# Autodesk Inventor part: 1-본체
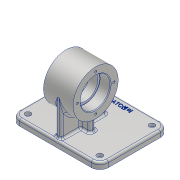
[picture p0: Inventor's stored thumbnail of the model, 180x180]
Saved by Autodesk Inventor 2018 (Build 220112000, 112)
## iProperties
Created: 2019-09
Part Number: 1-본체
Material: 알루미늄 6061
Document SubType Name: Modeling
Designer: USER
Density: 2.7 g/cm^3
Appearance: 알루미늄 - 평지
Mass: 554.62 g
Surface Area: 495.884 cm^2
Volume: 205.415 cm^3
Author: USER
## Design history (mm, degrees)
sketch "스케치1"
  geometry: L1 (-63, -49)-(63, -49); L2 (63, -49)-(63, 49); L3 (63, 49)-(-63, 49); L4 (-63, 49)-(-63, -49); L5 (-63, -49)-(63, 49); L6 (63, -49)-(-63, 49); 1 further point
  constraints: 12 end point, 2 midpoint, 2 parallel, 1 horizontal, 1 perpendicular
  dimensions: "d0" = 126 distance of L2.end L3.end; "d1" = 98 distance of L1.end L2.end
extrude "돌출1" new body sketch "스케치1" distance "d2" = 9; taper "d3" = 0 deg
sketch "스케치2"
  geometry: L1 (-49, 0)-(-49, 9) reference; L2 (49, 0)-(-49, 0) reference; C1 r 32 at (-13, 59); 1 further point
  constraints: 1 centre point
  dimensions: "d4" = 36 distance from line of L1 C1.centre; "d5" = 64 diameter of C1; "d6" = 59 distance from line of L2 C1.centre
extrude "돌출2" join sketch "스케치2" stored distance "d7" = 42; taper "d8" = 0 deg
sketch "스케치3"
  geometry: L1 (-45, 59)-(19, 59); L2 (19, 59)-(19, 0); L3 (19, 0)-(-45, 0); L4 (-45, 0)-(-45, 59); 2 further points
  constraints: 8 end point, 2 parallel, 1 horizontal, 1 horizontal alignment, 1 perpendicular, 1 other
  dimensions: "d9" = 64 distance between parallel lines of L2 L4; "d10" = 59 distance between parallel lines of L3 L1
extrude "돌출3" join sketch "스케치3" stored distance "d11" = 8; taper "d12" = 0 deg
sketch "스케치4"
  geometry: L1 (49, 0)-(-49, 0) reference; L2 (-17, 59)-(-9, 59); L3 (-9, 59)-(-9, 0); L4 (-9, 0)-(-17, 0); L5 (-17, 0)-(-17, 59); L6 (-49, 0)-(-49, 9) reference; L7 (-49, 9)-(-45, 9) reference; L8 (-45, 9)-(-45, 59) reference; L9 (19, 59)-(19, 9) reference; L10 (19, 9)-(49, 9) reference; L11 (49, 9)-(49, 0) reference; L12 (49, 0)-(-49, 0) reference; L13 (-49, 0)-(-49, 9) reference; L14 (-49, 9)-(-45, 9) reference; L15 (-45, 9)-(-45, 59) reference; L16 (19, 59)-(19, 9) reference; L17 (19, 9)-(49, 9) reference; L18 (49, 9)-(49, 0) reference; L19 (49, 0)-(-49, 0) reference; A1 r 32 centre (-13, 59) between (19, 59) and (-45, 59) reference; A2 r 32 centre (-13, 59) between (19, 59) and (-45, 59) reference; 1 further point
  constraints: 8 end point, 2 parallel, 1 horizontal, 1 perpendicular, 1 point on line
  dimensions: "d13" = 8 distance between parallel lines of L3 L5; "d14" = 59 distance between parallel lines of L1 L2; "d15" = 4 distance from line of L3 A1.centre
extrude "돌출4" join sketch "스케치4" stored distance "d16" = 34; taper "d17" = 0 deg
sketch "스케치5"
  geometry: C1 r 32 at (0, 0) reference; 2 further points
  constraints: 1 coincident
hole "구멍1" sketch "스케치5" at (0, 0) diameter "d18" = 36; stored, may be unused: countersink angle "d22" = 90 deg, drill point angle "d24" = 118 deg; dims "d19" = 6, "d20" = 42, "d21" = 15, "d23" = 36
node "작업 평면1"
sketch "스케치6" dims "d25" = 52
  geometry: A1 r 32 centre (0, 0) between (-31.749, -4) and (0, -32) reference; 3 further points
  constraints: 1 coincident, 1 horizontal alignment, 2 other
hole "구멍2" sketch "스케치6" at (26, 0) diameter "d26" = 3.242; stored, may be unused: countersink angle "d30" = 90 deg, drill point angle "d32" = 118 deg; dims "d27" = 8, "d28" = 42, "d29" = 15, "d31" = 10
sketch "스케치7"
  geometry: L1 (4, -9)-(17, -9) reference; L2 (17, -9)-(17, -17) reference; L3 (17, -17)-(4, -17) reference; L4 (4, -17)-(4, -45) reference; L5 (4, -45)-(-4, -45) reference; L6 (-4, -45)-(-4, -17) reference; L7 (-4, -17)-(-17, -17) reference; L8 (-17, -17)-(-17, -9) reference; L9 (-17, -9)-(-4, -9) reference; L10 (-4, -9)-(-4, 19) reference; L11 (-4, 19)-(4, 19) reference; L12 (4, 19)-(4, -9) reference; L13 (-63, -49)-(-63, 49) reference; L14 (-63, 49)-(63, 49) reference; L15 (63, 49)-(63, -49) reference; L16 (63, -49)-(-63, -49) reference; 5 further points
  dimensions: "d38" = 102 distance of point (-51, 37) point (51, 37); "d39" = 51 horizontal distance of point (0, 0) point (-51, 37) (= 0.5 x d38); "d40" = 102 distance of point (51, -37) point (-51, -37) (= d38); "d41" = 51 horizontal distance of point (0, 0) point (-51, -37) (= d39); "d42" = 74 distance of point (-51, -37) point (-51, 37); "d43" = 37 vertical distance of point (0, 0) point (-51, 37) (= 0.5 x d42)
hole "구멍3" sketch "스케치7" at (-51, 37), (51, 37), (51, -37), (-51, -37) diameter "d44" = 4.5; stored, may be unused: countersink angle "d48" = 90 deg, drill point angle "d50" = 118 deg; dims "d45" = 8, "d46" = 8, "d47" = 4.4, "d49" = 10
fillet "모깎기1" dims "d51" = 12
fillet "모깎기2" dims "d52" = 3
fillet "모깎기3" dims "d53" = 3
fillet "모깎기4" dims "d54" = 3
chamfer "모따기1" distance "d55" = 1; stored, may be unused: second distance "d56" = 2, angle "d57" = 45 deg
fillet "모깎기5" dims "d58" = 0.3
node "작업 평면2"
sketch "스케치8"
  geometry: L1 (63, -37)-(63, 37) reference; L2 (51, 49)-(-51, 49) reference; 2 further points
  constraints: 1 other
  dimensions: "d60" = 63 distance from line of L1 point (0, 39); "d61" = 10 distance from line of L2 point (0, 39)
feature "엠보싱1" sketch "스케치8" dims "d0" = 126, "d1" = 98, "d11" = 8, "d62" = 0.5, "d63" = 0
node "솔리드1"
mirror "미러1"
pattern_circular "원형 패턴1" dims angle "d34" = 360 deg
mirror "미러2"
node "절단 모서리 투영1"
node "절단 모서리 투영2"
node "절단 모서리 투영3"
other parameters: "d59" = 7.25
